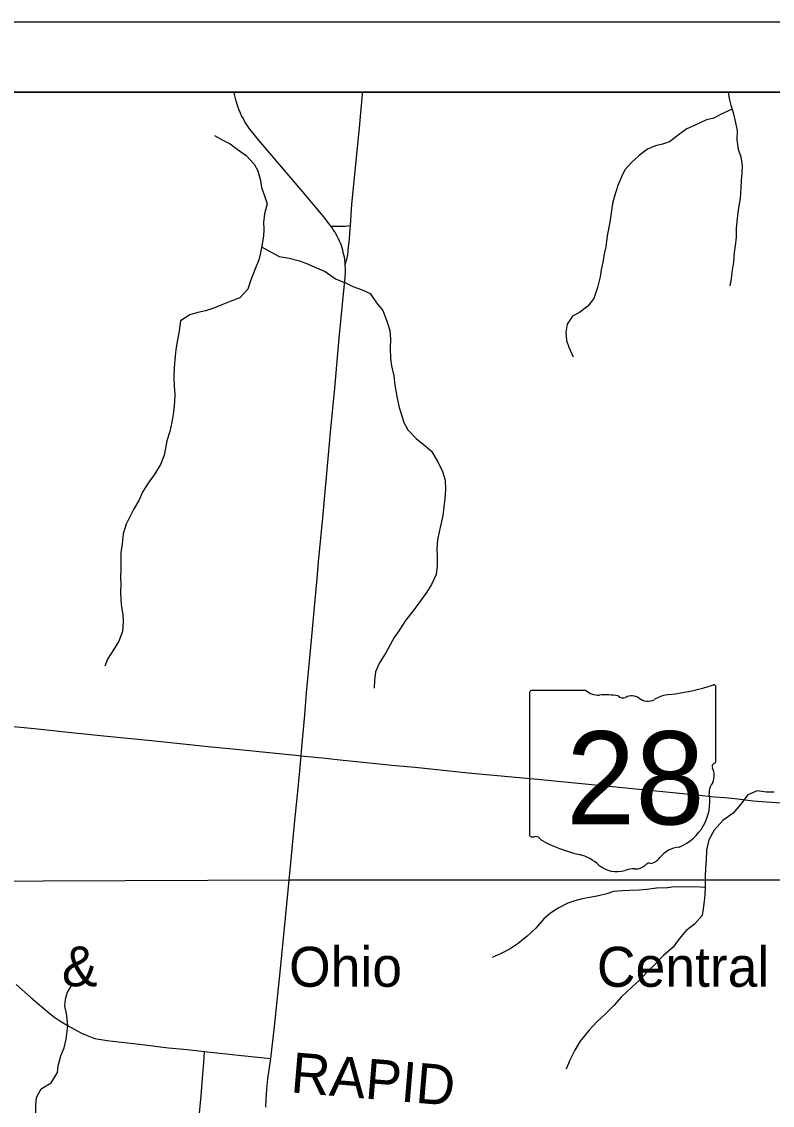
# Model space of a CAD drawing. Extents: x 0 to 48.6, y 0 to 22.
# Drawn here: x 3.078 to 4.141, y 19.466 to 21 of the extents above; entities that cross this region are included whole.
import ezdxf

# ---------------------------------------------------------------- set-up
doc = ezdxf.new("R2010")
doc.units = 0
for name, color, linetype in [('GM_X_Corporation', 7, 'Continuous'), ('GM_X_County_Road', 7, 'Continuous'), ('GM_X_Minor_River', 7, 'Continuous'), ('GM_X_Rail_Line', 7, 'Continuous'), ('GM_X_Rail_Line_Text', 7, 'Continuous'), ('GM_X_State_Location', 7, 'Continuous'), ('GM_X_State_Route', 7, 'Continuous'), ('GM_X_State_Shield', 7, 'Continuous'), ('GM_X_Township_Road', 7, 'Continuous'), ('GM_X_Township_Road_Text', 7, 'Continuous'), ('SH_Data', 7, 'Continuous')]:
    doc.layers.add(name, color=color, linetype=linetype)

msp = doc.modelspace()

# ---------------------------------------------------------------- linework, layer by layer
at = {"layer": 'GM_X_Corporation'}
for points in [[(8.9, 20.9), (2.1, 20.9), (2.1, 14.1)], [(5.5264, 17.0064), (5.8387, 17.2541), (6.5365, 17.7727), (6.4996, 17.9212), (6.3396, 18.6531), (6.2759, 18.9159), (6.0412, 19.8859), (5.8236, 20.7829), (5.795, 20.9), (2.1, 20.9), (2.1, 14.1)]]:
    msp.add_lwpolyline(points, dxfattribs=at)
at = {"layer": 'GM_X_County_Road'}
for points in [[(3.07, 19.6367), (3.0905, 19.6187), (3.1004, 19.6101), (3.1181, 19.5954), (3.125, 19.5901), (3.1317, 19.5855), (3.1367, 19.5824), (3.1428, 19.5786), (3.1471, 19.5762), (3.1531, 19.5729), (3.1573, 19.5707), (3.1625, 19.568), (3.1705, 19.5644), (3.1775, 19.5617), (3.1813, 19.5605), (3.1866, 19.5594), (3.1931, 19.5584), (3.199, 19.5576), (3.2151, 19.5554), (3.2484, 19.5516), (3.286, 19.5473), (3.312, 19.5446), (3.3367, 19.5419)], [(3.3273, 19.4298), (3.332, 19.4793), (3.3339, 19.5035), (3.3356, 19.5264), (3.3367, 19.5419)], [(3.3367, 19.5419), (3.3892, 19.5362), (3.4306, 19.5318)]]:
    msp.add_lwpolyline(points, dxfattribs=at)
at = {"layer": 'GM_X_Minor_River'}
for points in [[(4.0782, 20.9), (4.0796, 20.8913), (4.0822, 20.8818), (4.0854, 20.8715), (4.0876, 20.8609), (4.0908, 20.846), (4.0906, 20.8327), (4.0923, 20.8194), (4.0964, 20.8087), (4.0981, 20.7962), (4.0976, 20.7848), (4.0967, 20.7753), (4.0962, 20.7647), (4.0952, 20.7495), (4.0935, 20.7393), (4.0919, 20.7295), (4.0906, 20.7173), (4.0897, 20.7071), (4.0895, 20.695), (4.0882, 20.6828), (4.0869, 20.673), (4.0856, 20.6593), (4.0835, 20.6453), (4.0823, 20.6358), (4.0806, 20.626)], [(4.084, 20.8761), (4.0683, 20.8691), (4.058, 20.8635), (4.0477, 20.861), (4.0313, 20.8536), (4.0198, 20.8481), (4.0091, 20.8406), (3.9952, 20.8298), (3.9853, 20.8265), (3.9754, 20.824), (3.964, 20.8196), (3.9521, 20.8106), (3.9417, 20.8009), (3.932, 20.7904), (3.927, 20.7802), (3.9219, 20.7681), (3.9171, 20.753), (3.9143, 20.7424), (3.9126, 20.7291), (3.9105, 20.7163), (3.9069, 20.6966), (3.9048, 20.6814), (3.9027, 20.6712), (3.9007, 20.6594), (3.8986, 20.6485), (3.897, 20.6386), (3.8933, 20.6235), (3.8882, 20.608), (3.8797, 20.5971), (3.8678, 20.5881), (3.8579, 20.5829), (3.8501, 20.5716), (3.8484, 20.5603), (3.8494, 20.5485), (3.8527, 20.539), (3.8586, 20.5256)], [(3.3508, 20.8389), (3.3625, 20.8323), (3.3731, 20.8269), (3.3832, 20.8195), (3.3956, 20.8106), (3.4072, 20.7983), (3.4124, 20.7888), (3.416, 20.775), (3.4174, 20.7652), (3.4218, 20.7533), (3.4255, 20.7423), (3.4219, 20.7279), (3.4202, 20.7158), (3.4208, 20.7063), (3.4203, 20.6964), (3.4183, 20.6854), (3.4162, 20.6729), (3.4138, 20.6627), (3.4075, 20.6476), (3.402, 20.6329), (3.398, 20.6212), (3.3869, 20.6092), (3.3731, 20.6036), (3.3613, 20.5992), (3.3487, 20.5937), (3.338, 20.5908), (3.3273, 20.5883), (3.3159, 20.585), (3.3029, 20.5765), (3.3008, 20.5624), (3.2983, 20.5496), (3.2962, 20.5359), (3.2954, 20.5265), (3.2936, 20.5102), (3.2934, 20.4957), (3.294, 20.484), (3.2946, 20.4722), (3.2945, 20.4616), (3.2928, 20.4472), (3.2903, 20.4328), (3.2878, 20.4195), (3.2835, 20.4067), (3.2815, 20.3961), (3.2798, 20.3862), (3.2743, 20.373), (3.2665, 20.3598), (3.2572, 20.3466), (3.2495, 20.335), (3.244, 20.3221), (3.2362, 20.3093), (3.2308, 20.2988), (3.2257, 20.2886), (3.2217, 20.2746), (3.2204, 20.2606), (3.2183, 20.2481), (3.2182, 20.2382), (3.2184, 20.2249), (3.2179, 20.2139), (3.2181, 20.2029), (3.218, 20.1926), (3.2182, 20.1805), (3.2192, 20.171), (3.2213, 20.1607), (3.2216, 20.1505), (3.2206, 20.1364), (3.2155, 20.1228), (3.2078, 20.1104), (3.1996, 20.0976), (3.1957, 20.0874)], [(3.4176, 20.6814), (3.4427, 20.6677), (3.4567, 20.6652), (3.4711, 20.6612), (3.4825, 20.6573), (3.493, 20.6526), (3.5074, 20.6463), (3.5224, 20.6359), (3.5372, 20.6296), (3.547, 20.6249), (3.5602, 20.6202), (3.5715, 20.6151), (3.5805, 20.6017), (3.5894, 20.591), (3.5949, 20.5761), (3.5993, 20.5628), (3.6003, 20.5506), (3.5997, 20.5377), (3.5999, 20.5229), (3.6017, 20.5126), (3.6049, 20.4985), (3.6059, 20.489), (3.6077, 20.4769), (3.6102, 20.4647), (3.6123, 20.4536), (3.6156, 20.4433), (3.6192, 20.4327), (3.6248, 20.4223), (3.6364, 20.41), (3.6462, 20.4016), (3.6582, 20.3919), (3.6671, 20.377), (3.6737, 20.3633), (3.6774, 20.3507), (3.678, 20.3374), (3.677, 20.3249), (3.6754, 20.3131), (3.674, 20.3006), (3.6712, 20.2881), (3.6692, 20.2775), (3.6668, 20.2665), (3.6658, 20.2537), (3.6661, 20.2434), (3.6663, 20.2294), (3.6646, 20.2172), (3.6583, 20.2029), (3.6509, 20.192), (3.6424, 20.1799), (3.6324, 20.1656), (3.6212, 20.1521), (3.613, 20.1389), (3.6053, 20.128), (3.5998, 20.1175), (3.594, 20.1073), (3.5843, 20.0911), (3.5788, 20.0794), (3.5775, 20.0676), (3.577, 20.0563)], [(4.1432, 19.9089), (4.1326, 19.909), (4.1193, 19.9111), (4.1063, 19.9055), (4.0959, 19.8916), (4.0851, 19.8792), (4.0709, 19.8688), (4.0582, 19.8553), (4.0508, 19.8417), (4.0476, 19.827), (4.047, 19.8125), (4.0461, 19.8015), (4.0455, 19.7898), (4.0457, 19.7742), (4.0452, 19.7644), (4.0443, 19.7549), (4.0427, 19.7439), (4.0414, 19.7344), (4.0306, 19.7224), (4.0183, 19.7127), (4.0075, 19.6996), (4.0005, 19.6898), (3.9867, 19.6778), (3.9748, 19.6654), (3.9636, 19.6549), (3.9521, 19.6422), (3.9417, 19.6332), (3.9274, 19.6194), (3.9167, 19.6073), (3.9043, 19.5946), (3.8924, 19.5837), (3.8808, 19.5714), (3.8689, 19.5567), (3.8611, 19.5439), (3.8541, 19.5296)], [(4.0457, 19.7742), (4.0313, 19.7748), (4.015, 19.7746), (4.0017, 19.7748), (3.9922, 19.7738), (3.9766, 19.7732), (3.9633, 19.7711), (3.9522, 19.7701), (3.9386, 19.7699), (3.9283, 19.7693), (3.9161, 19.7683), (3.9066, 19.765), (3.8948, 19.7621), (3.8822, 19.76), (3.8715, 19.7579), (3.8613, 19.755), (3.8513, 19.7517), (3.8376, 19.7446), (3.8268, 19.7376), (3.8172, 19.7297), (3.8057, 19.7166), (3.7937, 19.705), (3.7807, 19.6949), (3.7696, 19.6871), (3.757, 19.6804), (3.744, 19.6749)], [(3.098, 19.4547), (3.0978, 19.4657), (3.0987, 19.4767), (3.1057, 19.4888), (3.1195, 19.4977), (3.1288, 19.512), (3.1297, 19.5215), (3.1333, 19.5359), (3.138, 19.5472), (3.1408, 19.5593), (3.1433, 19.5783), (3.142, 19.5927), (3.1391, 19.6064), (3.14, 19.6159), (3.1428, 19.6257), (3.1506, 19.6385)], [(3.8541, 19.5296), (3.849, 19.5167)]]:
    msp.add_lwpolyline(points, dxfattribs=at)
at = {"layer": 'GM_X_Rail_Line'}
msp.add_lwpolyline([(2.1, 19.7643), (2.1011, 19.7645), (2.172, 19.7738), (2.2311, 19.7779), (2.3038, 19.7803), (2.4027, 19.7791), (2.7583, 19.782), (3.4579, 19.785), (4.2295, 19.785), (4.6206, 19.7852), (5.0462, 19.7937), (5.6922, 19.8043), (6.0216, 19.8102), (6.7352, 19.82), (7.2096, 19.8291), (8.1004, 19.8459), (8.9, 19.8619)], dxfattribs=at)
at = {"layer": 'GM_X_State_Route'}
for points in [[(3.4237, 19.4632), (3.4237, 19.466), (3.4239, 19.4712), (3.4241, 19.476), (3.4245, 19.4801), (3.4251, 19.489), (3.4266, 19.5032), (3.4306, 19.5318), (3.4359, 19.5771), (3.4438, 19.6544), (3.4514, 19.7311), (3.4551, 19.77), (3.4594, 19.8139), (3.4642, 19.864), (3.4684, 19.9054), (3.4718, 19.9394), (3.4736, 19.9606), (3.4742, 19.9673), (3.4787, 20.0187), (3.4814, 20.0496), (3.4882, 20.1245), (3.4912, 20.1554), (3.495, 20.1963), (3.4963, 20.2111), (3.4984, 20.2352), (3.5045, 20.2977), (3.5125, 20.3868), (3.5152, 20.419), (3.5212, 20.4809), (3.5276, 20.552), (3.5342, 20.6194), (3.5359, 20.6373), (3.5363, 20.6466), (3.5362, 20.6507), (3.5361, 20.6546), (3.5358, 20.659), (3.5354, 20.6626), (3.5348, 20.6664), (3.5342, 20.6699), (3.5333, 20.6734), (3.5326, 20.6764), (3.5315, 20.6799), (3.5305, 20.6829), (3.5291, 20.6863), (3.528, 20.6892), (3.5264, 20.6926), (3.5246, 20.6964), (3.5228, 20.6996), (3.5213, 20.7023), (3.5196, 20.7049), (3.5176, 20.708), (3.5158, 20.7104), (3.5152, 20.7112), (3.5125, 20.7147), (3.5105, 20.7174), (3.5071, 20.7217), (3.5032, 20.7265), (3.5004, 20.7299), (3.476, 20.759), (3.4293, 20.8138), (3.4108, 20.8356), (3.4033, 20.8448), (3.4006, 20.8485), (3.3982, 20.8519), (3.3959, 20.8553), (3.3934, 20.8592), (3.3913, 20.8632), (3.3892, 20.8669), (3.3876, 20.8703), (3.3858, 20.8745), (3.3844, 20.8785), (3.3828, 20.8833), (3.3816, 20.8874), (3.3801, 20.8931), (3.3792, 20.8971), (3.3786, 20.9)], [(3.0528, 20.0036), (3.1052, 19.9983), (3.1435, 19.9942), (3.1941, 19.9889), (3.2664, 19.9816), (3.3418, 19.9737), (3.3956, 19.9684), (3.4283, 19.9651), (3.466, 19.9613), (3.4736, 19.9606), (3.5082, 19.957), (3.5329, 19.9544), (3.6071, 19.9469), (3.6349, 19.9443), (3.7103, 19.9366), (3.8081, 19.9274), (3.9286, 19.9157), (4.0331, 19.9053), (4.0591, 19.9026), (4.0733, 19.9013), (4.0875, 19.8999), (4.1135, 19.897), (4.1327, 19.8955), (4.1538, 19.8938)]]:
    msp.add_lwpolyline(points, dxfattribs=at)
at = {"layer": 'GM_X_State_Shield'}
for p, q in [((4.0607, 19.9531), (4.0607, 20.0578)), ((3.797, 20.0494), (3.797, 19.8493)), ((3.8769, 20.0528), (3.7996, 20.0528)), ((4.0607, 19.9531), (4.0607, 19.9531))]:
    msp.add_line(p, q, dxfattribs=at)
for centre, radius, start, end in [((3.9668, 20.3257), 0.2796, 275.8445, 288.9065), ((4.0578, 20.0582), 0.00294, 351.8621, 97.738), ((3.8001, 20.0498), 0.00305, 98.1301, 188.1301), ((3.8952, 20.0761), 0.0296, 231.6195, 271.1119), ((3.9051, 19.9405), 0.1064, 80.4867, 94.9883), ((3.9292, 20.0509), 0.00855, 219.7921, 297.1024), ((3.9418, 20.0277), 0.0178, 54.4667, 119.1411), ((3.9647, 20.0594), 0.0214, 233.8562, 294.8282), ((4.0024, 19.9917), 0.0563, 97.3462, 120.7689), ((4.06, 19.9454), 0.00454, 107.944, 210.337), ((4.0576, 19.9527), 0.00314, 289.6038, 7.7341), ((4.0311, 19.9322), 0.0273, 340.033, 23.6496), ((4.0712, 19.9093), 0.0198, 136.8065, 186.9296), ((3.9824, 19.896), 0.0699, 292.3089, 8.9858), ((3.8001, 19.8488), 0.00308, 171.9584, 258.3066), ((3.8006, 19.8693), 0.0235, 267.339, 280.6039), ((3.8054, 19.8377), 0.00848, 29.7484, 93.2717), ((3.9124, 20.0175), 0.2019, 240.4129, 257.1985), ((4.0119, 19.7931), 0.0383, 94.4031, 142.5768), ((3.8522, 19.7594), 0.0632, 47.1842, 75.836), ((3.966, 19.8024), 0.00601, 65.7517, 132.6484), ((3.9634, 19.8299), 0.0226, 282.8732, 323.2771), ((3.9206, 19.8367), 0.0401, 230.7004, 286.2918), ((3.9437, 19.7675), 0.0329, 85.6951, 111.2099), ((3.9466, 19.8217), 0.0214, 268.777, 315.5493)]:
    msp.add_arc(centre, radius, start, end, dxfattribs=at)
at = {"layer": 'GM_X_Township_Road'}
for points in [[(3.5434, 20.7116), (3.5456, 20.741), (3.5491, 20.7794), (3.5561, 20.8499), (3.5605, 20.8975), (3.5607, 20.9)], [(3.5158, 20.7104), (3.5211, 20.7104), (3.5249, 20.7104), (3.529, 20.7104), (3.5318, 20.7103), (3.5341, 20.7104), (3.5361, 20.7106), (3.5393, 20.7109), (3.5434, 20.7116)], [(3.5361, 20.6546), (3.5378, 20.6621), (3.5386, 20.6658), (3.5392, 20.6683), (3.5396, 20.6701), (3.5402, 20.6746), (3.5404, 20.676), (3.5413, 20.685), (3.5419, 20.6915), (3.5426, 20.7009), (3.5434, 20.7116)]]:
    msp.add_lwpolyline(points, dxfattribs=at)
at = {"layer": 'SH_Data'}
for p, q in [((2, 21), (9, 21)), ((2.1, 20.9), (8.9, 20.9))]:
    msp.add_line(p, q, dxfattribs=at)

# ---------------------------------------------------------------- texts
at = {"layer": 'GM_X_Rail_Line_Text'}
for s, height, p in [('&', 0.0566, (3.1349, 19.6342)), ('Ohio', 0.05663, (3.4565, 19.6335)), ('Central', 0.05663, (3.8924, 19.6335))]:
    msp.add_text(s, height=height, rotation=0, dxfattribs=at).set_placement(p)
at = {"layer": 'GM_X_State_Location'}
for s in ['s', 'r']:
    msp.add_text(s, height=0.000189, dxfattribs=at).set_placement((3.9259, 19.936))
msp.add_text('28', height=0.000189, rotation=0, dxfattribs=at).set_placement((3.8782, 19.9222))
at = {"layer": 'GM_X_State_Shield'}
msp.add_text('28', height=0.13184, dxfattribs=at).set_placement((3.8488, 19.8634))
at = {"layer": 'GM_X_Township_Road_Text'}
msp.add_text('RAPID', height=0.05682, rotation=355.2171, dxfattribs=at).set_placement((3.4577, 19.4842))

doc.saveas('drawing.dxf')
